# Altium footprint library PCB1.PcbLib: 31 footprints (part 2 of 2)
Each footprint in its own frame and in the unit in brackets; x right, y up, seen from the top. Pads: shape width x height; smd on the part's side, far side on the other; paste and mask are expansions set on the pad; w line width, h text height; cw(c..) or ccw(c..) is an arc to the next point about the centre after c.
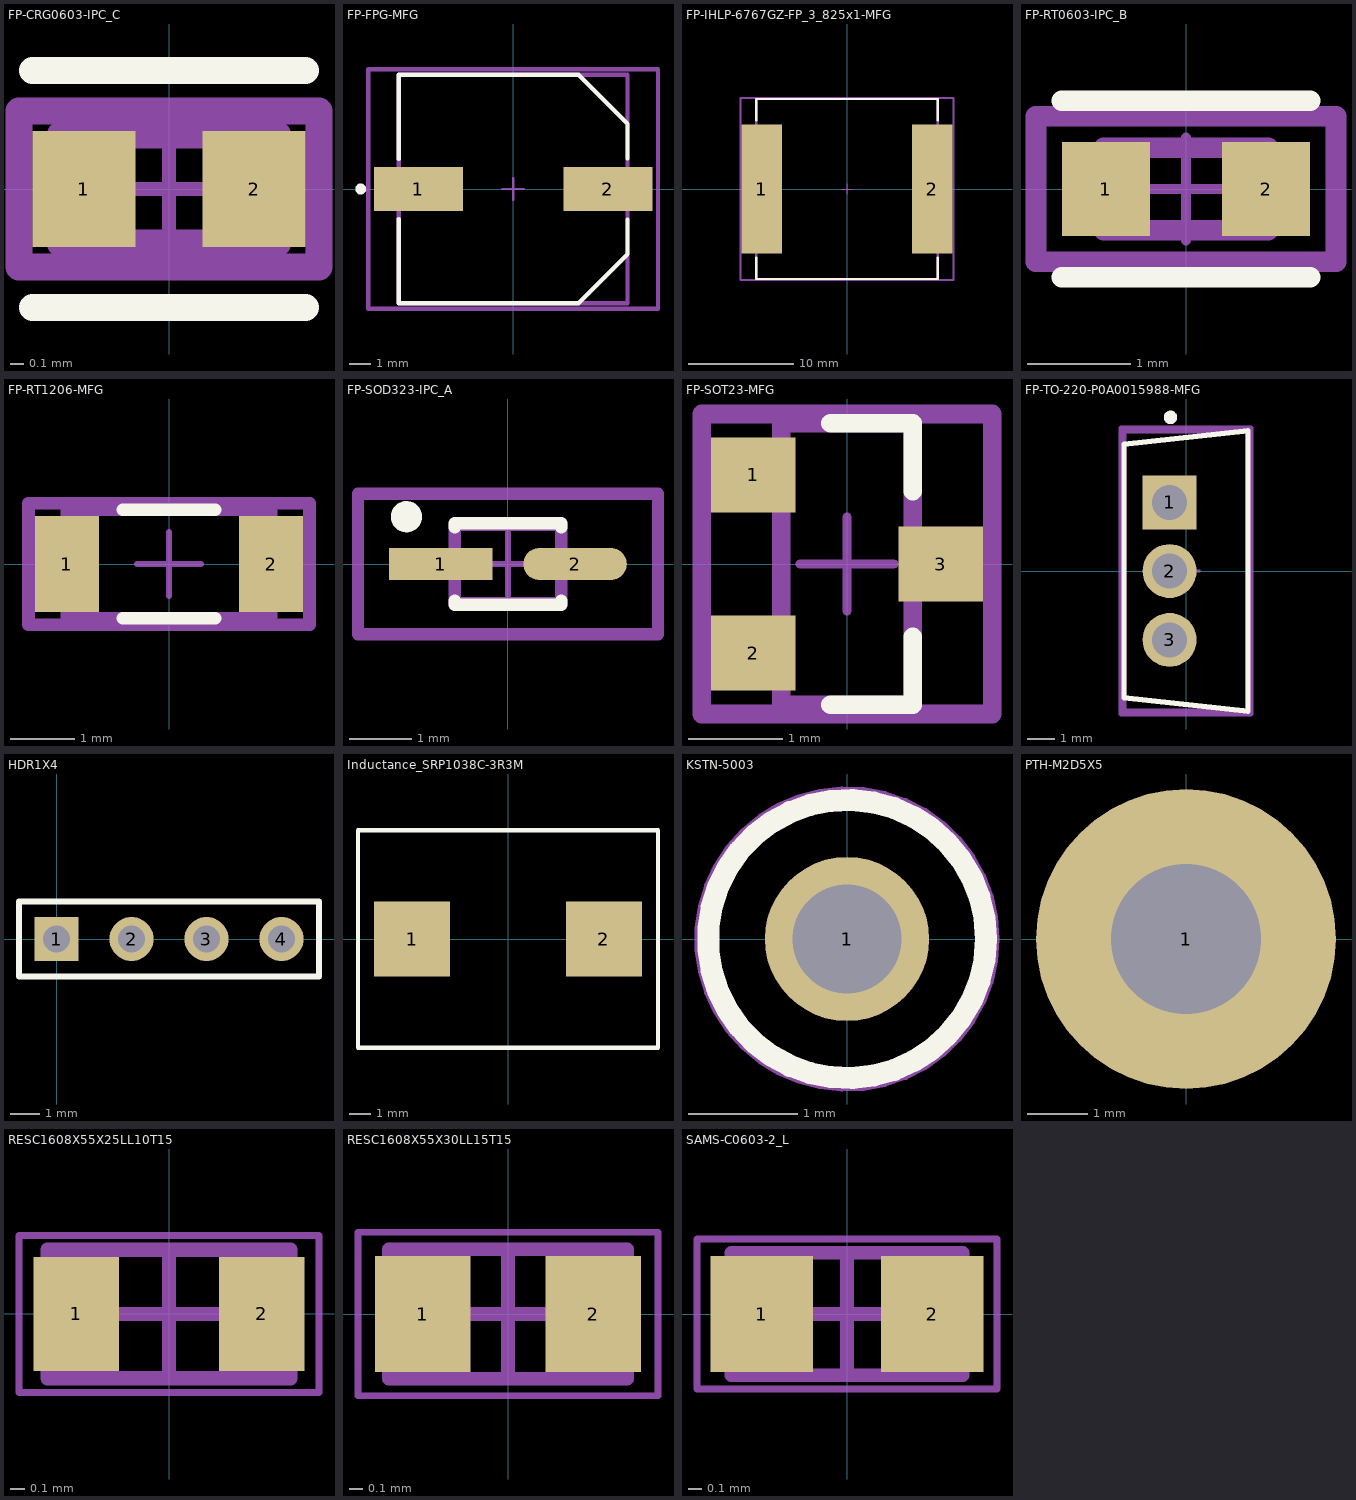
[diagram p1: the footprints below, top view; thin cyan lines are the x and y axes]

## FP-CRG0603-IPC_C [mm]
pads (2):
  rect 0.758x0.858 smd paste+0 mask+0: 1(-0.627,0) 2(0.627,0)
Top Overlay:
  lines w0.2: -1.006,-0.875 1.006,-0.875 ; -1.006,0.875 1.006,0.875
Top Assembly:
  lines w0.2: -1.106,-0.575 1.106,-0.575 1.106,0.575 -1.106,0.575 -1.106,-0.575
  text ".Designator" at 0,0.188 h1
Top 3D Body:
  lines w0.2: -0.8,-0.4 0.8,-0.4 0.8,0.4 -0.8,0.4 -0.8,-0.4
Top Courtyard:
  lines w0.2: -1.106,-0.575 1.106,-0.575 1.106,0.575 -1.106,0.575 -1.106,-0.575
Top Component Center:
  lines w0.1: -0.5,0 0.5,0 ; 0,-0.5 0,0.5
3D body "Res_TE_Connectivity_CRG0603F1K0_eec.STEP": height 0.25, standoff 0, extent -1.106,-0.575 1.106,0.575

## FP-FPG-MFG [mm]
pads (2):
  rect 4.1x2 smd paste+0 mask+0: 1(-4.35,0) 2(4.35,0)
Top Overlay:
  circle w0.25: c-7,0 r0.125
  lines w0.2: -5.25,-1.375 -5.25,-5.25 3,-5.25 5.25,-3 5.25,-1.4 ; -5.25,1.375 -5.25,5.25 3,5.25 5.25,3 5.25,1.4
Top Assembly:
  lines w0.2: -6.65,-5.5 6.65,-5.5 6.65,5.5 -6.65,5.5 -6.65,-5.5
  text ".Designator" at 0,0.188 h1
Top 3D Body:
  lines w0.2: -5.25,-5.25 5.25,-5.25 5.25,5.25 -5.25,5.25 -5.25,-5.25
Top Courtyard:
  lines w0.2: -6.65,-5.5 6.65,-5.5 6.65,5.5 -6.65,5.5 -6.65,-5.5
Top Component Center:
  lines w0.1: -0.5,0 0.5,0 ; 0,-0.5 0,0.5
3D body "Cap_Panasonic_EEEFP1V331AP_eec.STEP": height 0.25, standoff 0, extent -6.65,-5.5 6.65,5.5

## FP-IHLP-6767GZ-FP_3_825x1-MFG [mm]
pads (2):
  rect 3.825x12.32 smd paste+0 mask+0: 1(-8.117,0) 2(8.117,0)
Top Overlay:
  lines w0.2: -8.638,-6.535 -8.638,-8.575 8.638,-8.575 8.638,-6.535 ; -8.638,6.535 -8.638,8.575 8.638,8.575 8.638,6.535
Top Assembly:
  lines w0.2: -10.13,-8.675 10.13,-8.675 10.13,8.675 -10.13,8.675 -10.13,-8.675
  text ".Designator" at 0,0.188 h1
Top 3D Body:
  lines w0.2: -8.638,-8.575 8.638,-8.575 8.638,8.575 -8.638,8.575 -8.638,-8.575
Top Courtyard:
  lines w0.2: -10.13,-8.675 10.13,-8.675 10.13,8.675 -10.13,8.675 -10.13,-8.675
Top Component Center:
  lines w0.1: -0.5,0 0.5,0 ; 0,-0.5 0,0.5
3D body "Ind_Vishay_IHLP6767GZER1R5M11_eec.STEP": height 0.25, standoff 0, extent -10.13,-8.675 10.13,8.675

## FP-RT0603-IPC_B [mm]
pads (2):
  rect 0.859x0.912 smd paste+0 mask+0: 1(-0.777,0) 2(0.777,0)
Top Overlay:
  lines w0.2: -1.206,-0.856 1.206,-0.856 ; -1.206,0.856 1.206,0.856
Top Assembly:
  lines w0.2: -1.456,-0.706 1.456,-0.706 1.456,0.706 -1.456,0.706 -1.456,-0.706
  text ".Designator" at 0,0.188 h1
Top 3D Body:
  lines w0.2: -0.8,-0.4 0.8,-0.4 0.8,0.4 -0.8,0.4 -0.8,-0.4
Top Courtyard:
  lines w0.2: -1.456,-0.706 1.456,-0.706 1.456,0.706 -1.456,0.706 -1.456,-0.706
Top Component Center:
  lines w0.1: -0.5,0 0.5,0 ; 0,-0.5 0,0.5
3D body "Res_Yageo_RT0603CRE0724K3L_eec.STEP": height 0.25, standoff 0, extent -1.456,-0.706 1.456,0.706

## FP-RT1206-MFG [mm]
pads (2):
  rect 1x1.5 smd paste+0 mask+0: 1(-1.6,0) 2(1.6,0)
Top Overlay:
  lines w0.2: -0.725,-0.85 0.725,-0.85 ; -0.725,0.85 0.725,0.85
Top Assembly:
  lines w0.2: -2.2,-0.95 2.2,-0.95 2.2,0.95 -2.2,0.95 -2.2,-0.95
  text ".Designator" at 0,0.188 h1
Top 3D Body:
  lines w0.2: -1.6,-0.85 1.6,-0.85 1.6,0.85 -1.6,0.85 -1.6,-0.85
Top Courtyard:
  lines w0.2: -2.2,-0.95 2.2,-0.95 2.2,0.95 -2.2,0.95 -2.2,-0.95
Top Component Center:
  lines w0.1: -0.5,0 0.5,0 ; 0,-0.5 0,0.5
3D body "Res_Yageo_RT1206WRB073K92L_eec.STEP": height 0.25, standoff 0, extent -2.2,-0.95 2.2,0.95

## FP-SOD323-IPC_A [mm]
pads (2):
  rect 1.655x0.516 smd paste+0 mask+0: 1(-1.075,0)
  rrect100% 1.655x0.516 smd paste+0 mask+0: 2(1.075,0)
Top Overlay:
  circle w0.25: c-1.627,0.758 r0.125
  lines w0.2: -0.85,-0.585 -0.85,-0.65 0.85,-0.65 0.85,-0.585 ; -0.85,0.585 -0.85,0.65 0.85,0.65 0.85,0.585
Top Assembly:
  lines w0.2: -2.403,-1.125 2.403,-1.125 2.403,1.125 -2.403,1.125 -2.403,-1.125
  text ".Designator" at 0,0 h1
Top 3D Body:
  lines w0.2: -0.85,-0.625 0.85,-0.625 0.85,0.625 -0.85,0.625 -0.85,-0.625
Top Courtyard:
  lines w0.2: -2.403,-1.125 2.403,-1.125 2.403,1.125 -2.403,1.125 -2.403,-1.125
Top Component Center:
  lines w0.1: -0.5,0 0.5,0 ; 0,-0.5 0,0.5

## FP-SOT23-MFG [mm]
pads (3):
  rect 0.9x0.8 smd paste+0 mask+0: 1(-1,0.95) 2(-1,-0.95) 3(1,0)
Top Overlay:
  lines w0.2: -0.175,-1.5 0.7,-1.5 0.7,-0.775 ; -0.175,1.5 0.7,1.5 0.7,0.775
Top Assembly:
  lines w0.2: -1.55,-1.6 1.55,-1.6 1.55,1.6 -1.55,1.6 -1.55,-1.6
  text ".Designator" at 0,0 h1
Top 3D Body:
  lines w0.2: -0.7,-1.5 0.7,-1.5 0.7,1.5 -0.7,1.5 -0.7,-1.5
Top Courtyard:
  lines w0.2: -1.55,-1.6 1.55,-1.6 1.55,1.6 -1.55,1.6 -1.55,-1.6
Top Component Center:
  lines w0.1: -0.5,0 0.5,0 ; 0,-0.5 0,0.5
3D body "Diode_Diodes_Inc_BZX84C18-7-F_eec.STEP": height 0.25, standoff 0, extent -1.55,-1.6 1.55,1.6

## FP-TO-220-P0A0015988-MFG [mm]
pads (3):
  rect 2x2 hole 1.3 paste-1000 mask+0: 1(-0.607,2.55)
  round 2 hole 1.3 paste-1000 mask+0: 2(-0.607,0) 3(-0.607,-2.55)
Top Overlay:
  circle w0.25: c-0.575,5.7 r0.125
  lines w0.2: -2.3,-4.7 2.3,-5.2 2.3,5.2 -2.3,4.7 -2.3,-4.7
Top Assembly:
  lines w0.2: -2.4,-5.3 2.4,-5.3 2.4,5.3 -2.4,5.3 -2.4,-5.3
  text ".Designator" at 0,0 h1
Top 3D Body:
  lines w0.2: -2.3,-5.2 2.3,-5.2 2.3,5.2 -2.3,5.2 -2.3,-5.2
Top Courtyard:
  lines w0.2: -2.4,-5.3 2.4,-5.3 2.4,5.3 -2.4,5.3 -2.4,-5.3
Top Component Center:
  lines w0.1: -0.5,0 0.5,0 ; 0,-0.5 0,0.5
3D body "Trans_STMicroelectronics_TIP31C_eec.STEP": height 0.25, standoff 0, extent -2.4,-5.3 2.4,5.3

## HDR1X4 [mm] "Connector; Header; 4 Position"
pads (4):
  rect 1.5x1.5 hole 0.9: 1(0,0)
  round 1.5 hole 0.9: 2(2.54,0) 3(5.08,0) 4(7.62,0)
Top Overlay:
  lines w0.2: -1.27,-1.27 8.89,-1.27 8.89,1.27 -1.27,1.27 -1.27,-1.27

## Inductance_SRP1038C-3R3M [mm]
pads (2):
  rect 3.55x3.5 smd: 1(-4.475,0) 2(4.475,0)
Top Overlay:
  lines w0.2: -7,-5.08 7,-5.08 7,5.08 -7,5.08 -7,0 -7,-5.08

## KSTN-5003 [mm] "Test Point, Through Hole, Dia 2.54mm"
height 4.57
pads (1):
  round 1.5 hole 1: 1(0,0)
Top Overlay:
  circle w0.2: c0,0 r1.27
Top 3D Body:
  circle w0.1: c0,0 r1.27
Top Courtyard:
  circle w0.05: c0,0 r1.37
  lines w0.1: -0.5,0 0.5,0 ; 0,-0.5 0,0.5
3D body "User Library-Test Point Keystone - 5003 ORANGE.STEP": height 4.57, standoff -3.05, extent -1.27,-1.27 1.27,1.27

## PTH-M2D5X5 [mm]
pads (1):
  round 5 hole 2.5: 1(0,0)
Top Designator:
  text ".Designator" at -1.397,2.921 h0.6

## RESC1608X55X25LL10T15 [mm] "Chip Resistor, 2-Leads, Body 1.60x0.80mm, IPC High Density"
height 0.55
pads (2):
  rect 0.6x0.8 smd: 1(-0.65,0) 2(0.65,0)
Top 3D Body:
  lines w0.1: -0.85,-0.45 0.85,-0.45 0.85,0.45 -0.85,0.45 -0.85,-0.45
Top Courtyard:
  lines w0.05: -1.05,-0.55 1.05,-0.55 1.05,0.55 -1.05,0.55 -1.05,-0.55
  lines w0.1: -0.45,0 0.45,0 ; 0,-0.45 0,0.45
3D body: height 0.55, standoff 0, extent 0.6,-0.45 0.85,0.45
3D body: height 0.55, standoff 0, extent -0.85,-0.45 -0.6,0.45
3D body: height 0.55, standoff 0, extent -0.6,-0.45 0.6,0.45

## RESC1608X55X30LL15T15 [mm] "Chip Resistor, 2-Leads, Body 1.60x0.80mm, IPC High Density"
height 0.55
pads (2):
  rect 0.7x0.85 smd: 1(-0.625,0) 2(0.625,0)
Top 3D Body:
  lines w0.1: -0.875,-0.475 0.875,-0.475 0.875,0.475 -0.875,0.475 -0.875,-0.475
Top Courtyard:
  lines w0.05: -1.1,-0.6 1.1,-0.6 1.1,0.6 -1.1,0.6 -1.1,-0.6
  lines w0.1: -0.475,0 0.475,0 ; 0,-0.475 0,0.475
3D body: height 0.55, standoff 0, extent 0.575,-0.475 0.875,0.475
3D body: height 0.55, standoff 0, extent -0.875,-0.475 -0.575,0.475
3D body: height 0.55, standoff 0, extent -0.575,-0.475 0.575,0.475

## SAMS-C0603-2_L [mm] "Chip Capacitor, 2-Leads, Body 1.70x0.90mm, IPC High Density"
height 0.9
pads (2):
  rect 0.75x0.85 smd: 1(-0.625,0) 2(0.625,0)
Top 3D Body:
  lines w0.1: -0.85,-0.45 -0.85,0.45 0.85,0.45 0.85,-0.45 -0.85,-0.45
Top Courtyard:
  lines w0.05: -1.1,-0.55 -1.1,0.55 1.1,0.55 1.1,-0.55 -1.1,-0.55
  lines w0.1: -0.45,0 0.45,0 ; 0,-0.45 0,0.45
3D body: height 0.9, standoff 0, extent -0.55,-0.45 0.55,0.45
3D body: height 0.9, standoff 0, extent -0.85,-0.45 -0.55,0.45
3D body: height 0.9, standoff 0, extent 0.55,-0.45 0.85,0.45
